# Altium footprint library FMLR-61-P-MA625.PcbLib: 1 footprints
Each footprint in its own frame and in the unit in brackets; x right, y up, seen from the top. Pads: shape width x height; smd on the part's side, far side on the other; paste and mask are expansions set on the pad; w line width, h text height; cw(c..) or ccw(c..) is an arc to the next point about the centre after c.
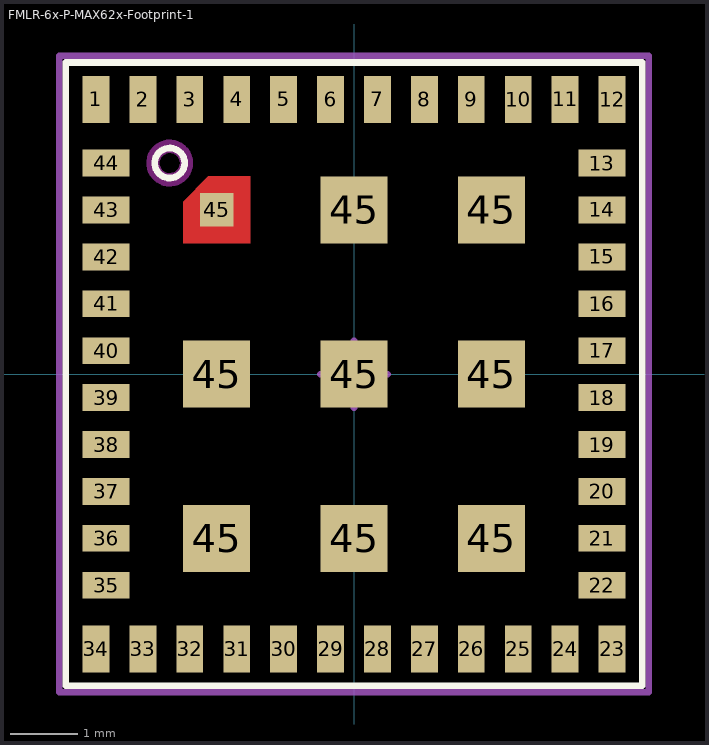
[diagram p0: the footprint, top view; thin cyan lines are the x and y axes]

## FMLR-6x-P-MAX62x-Footprint-1 [mm]
pads (53):
  rect 0.4x0.7 smd: 1(-3.85,4.1) 2(-3.15,4.1) 3(-2.45,4.1) 4(-1.75,4.1) 5(-1.05,4.1) 6(-0.35,4.1) 7(0.35,4.1) 8(1.05,4.1) 9(1.75,4.1) 10(2.45,4.1) 11(3.15,4.1) 12(3.85,4.1) 23(3.85,-4.1) 24(3.15,-4.1) 25(2.45,-4.1) 26(1.75,-4.1) 27(1.05,-4.1) 28(0.35,-4.1) 29(-0.35,-4.1) 30(-1.05,-4.1) 31(-1.75,-4.1) 32(-2.45,-4.1) 33(-3.15,-4.1) 34(-3.85,-4.1)
  rect 0.7x0.4 smd: 13(3.7,3.15) 14(3.7,2.45) 15(3.7,1.75) 16(3.7,1.05) 17(3.7,0.35) 18(3.7,-0.35) 19(3.7,-1.05) 20(3.7,-1.75) 21(3.7,-2.45) 22(3.7,-3.15) 35(-3.7,-3.15) 36(-3.7,-2.45) 37(-3.7,-1.75) 38(-3.7,-1.05) 39(-3.7,-0.35) 40(-3.7,0.35) 41(-3.7,1.05) 42(-3.7,1.75) 43(-3.7,2.45) 44(-3.7,3.15)
  rect 1x1 smd: 45(-2.05,-2.45) 45(-2.05,0) 45(0,-2.45) 45(0,0) 45(0,2.45) 45(2.05,-2.45) 45(2.05,0) 45(2.05,2.45)
  rect 0.5x0.5 smd: 45(-2.05,2.45)
Top Layer:
  region: -2.55,1.95 -1.55,1.95 -1.55,2.95 -2.175,2.95 -2.55,2.575
Top Overlay:
  circle w0.1: c-2.75,3.15 r0.224
  lines w0.1: -4.3,-4.65 4.3,-4.65 4.3,4.65 -4.3,4.65 -4.3,-4.65
Keep-Out Layer:
  circle w0.2: c-2.75,3.15 r0.25
Mechanical 15:
  lines w0.1: -0.5,0 0.5,0 ; 0,-0.5 0,0.5 ; -4.4,-4.746 4.4,-4.746 4.4,4.75 -4.4,4.75 -4.4,-4.746
3D body "FMLR-6x-P-MA62x.step": height 1.8, standoff 0.02, extent -4.3,-4.7 4.3,4.7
